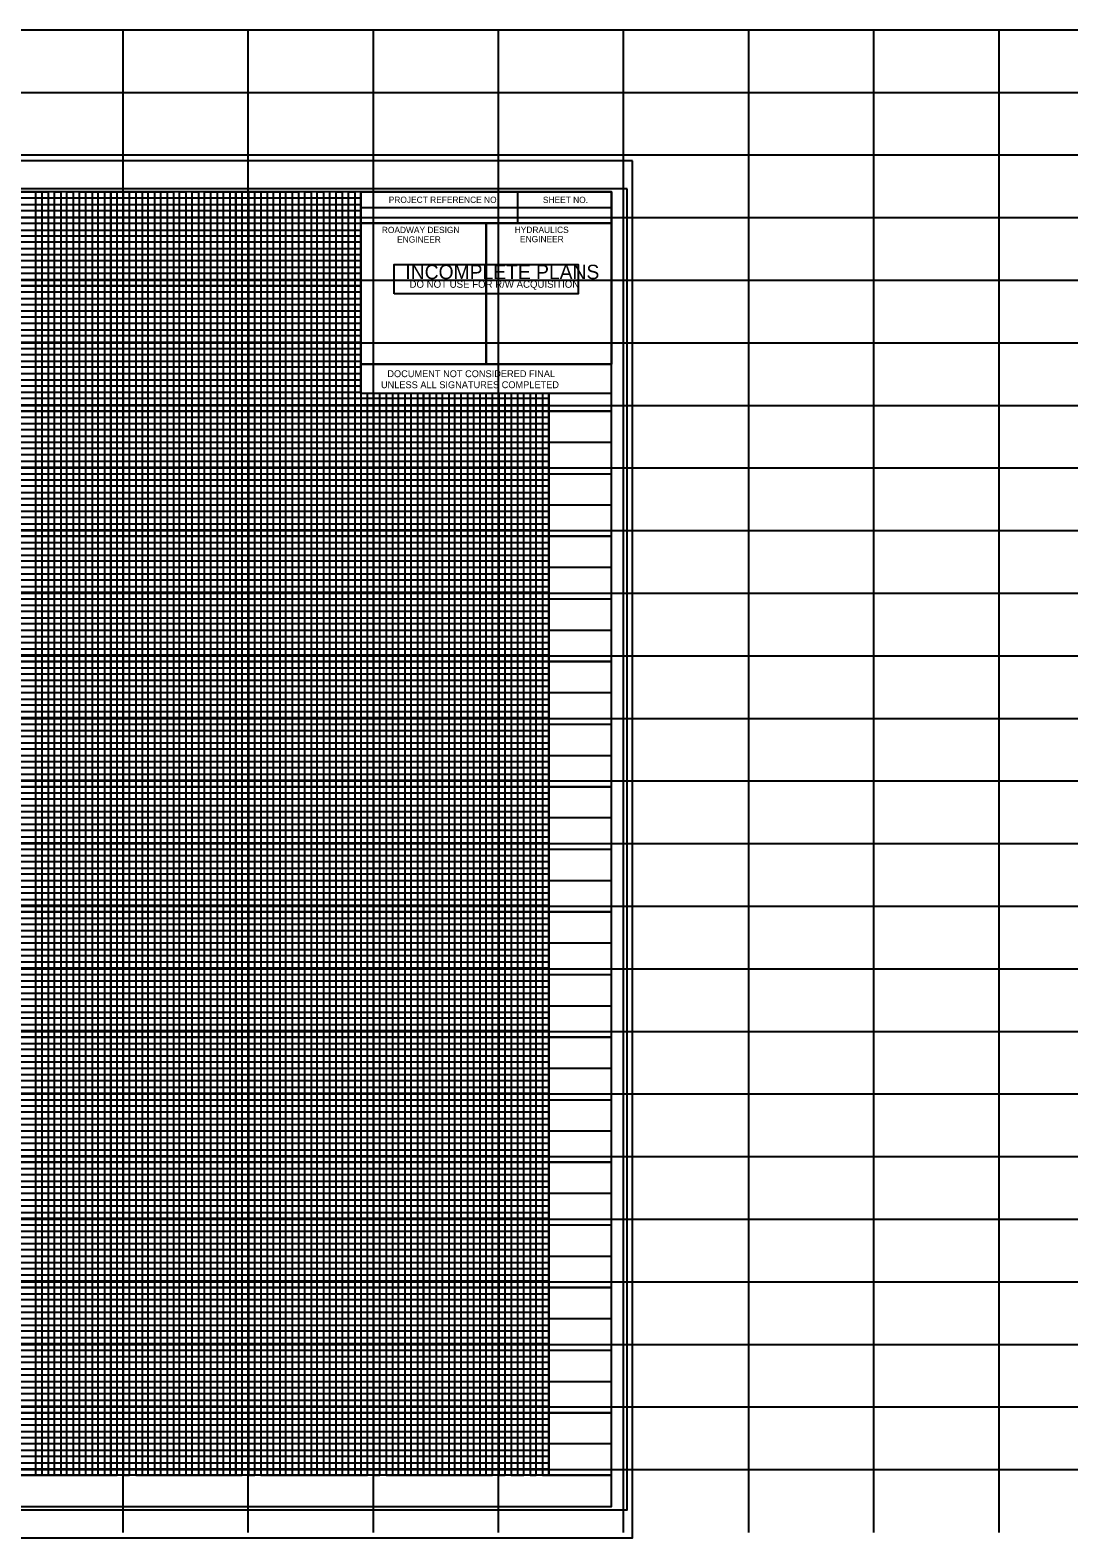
# Model space of a CAD drawing. Extents: x 553912 to 567693, y 512355 to 537539.
# Drawn here: x 560975 to 561805, y 521050 to 522255 of the extents above; entities that cross this region are included whole.
import ezdxf

# ---------------------------------------------------------------- set-up
doc = ezdxf.new("R2010")
doc.units = 0
for name, color, linetype in [('Default', 7, 'Continuous'), ('Old_Level_42', 7, 'Continuous'), ('Old_Level_51', 7, 'Continuous'), ('Old_Level_53', 7, 'Continuous'), ('Old_Level_54', 7, 'Continuous'), ('Prop ROW Permanent Easement CELL', 7, 'Continuous'), ('Sheet Profile Grid Major CELL', 7, 'Continuous'), ('Sheet Row Area Data CELL', 7, 'Continuous'), ('Sheet Sticker Exception Certification CELL', 7, 'Continuous'), ('Sheet Summary Guardrail CELL', 7, 'Continuous')]:
    doc.layers.add(name, color=color, linetype=linetype)

msp = doc.modelspace()

# ---------------------------------------------------------------- linework, layer by layer
at = {"layer": 'Default'}
for points in [[(561456.7, 522150.4), (559772.7, 522150.4), (559772.7, 521050.4), (561456.7, 521050.4)], [(561266.2, 522044.1), (561266.2, 522067.6), (561413.2, 522067.6), (561413.2, 522044.1)]]:
    msp.add_lwpolyline(points, close=True, dxfattribs=at)
at = {"layer": 'Old_Level_42'}
for p, q in [((560989.7, 522125.4), (560989.7, 521100.4)), ((561039.7, 522125.4), (561039.7, 521100.4)), ((561089.7, 522125.4), (561089.7, 521100.4)), ((561139.7, 522125.4), (561139.7, 521100.4)), ((561189.7, 522125.4), (561189.7, 521100.4)), ((559939.7, 522100.4), (561239.6, 522100.4)), ((559939.7, 522050.4), (561239.6, 522050.4)), ((559939.7, 522000.4), (561239.6, 522000.4)), ((561239.7, 521100.4), (561239.7, 521987.9)), ((561289.7, 521100.4), (561289.7, 521964.4)), ((561339.7, 521100.4), (561339.7, 521964.4)), ((561389.7, 521100.4), (561389.7, 521964.4)), ((559939.7, 521950.4), (561439.7, 521950.4)), ((559939.7, 521900.4), (561439.7, 521900.4)), ((559939.7, 521850.4), (561439.7, 521850.4)), ((559939.7, 521800.4), (561439.7, 521800.4)), ((559939.7, 521750.4), (561439.7, 521750.4)), ((559939.7, 521700.4), (561439.7, 521700.4)), ((559939.7, 521650.4), (561439.7, 521650.4)), ((559939.7, 521600.4), (561439.7, 521600.4)), ((559939.7, 521550.4), (561439.7, 521550.4)), ((559939.7, 521500.4), (561439.7, 521500.4)), ((559939.7, 521450.4), (561439.7, 521450.4)), ((559939.7, 521400.4), (561439.7, 521400.4)), ((559939.7, 521350.4), (561439.7, 521350.4)), ((559939.7, 521300.4), (561439.7, 521300.4)), ((559939.7, 521250.4), (561439.7, 521250.4)), ((559939.7, 521200.4), (561439.7, 521200.4)), ((559939.7, 521150.4), (561439.7, 521150.4))]:
    msp.add_line(p, q, dxfattribs=at)
at = {"layer": 'Old_Level_51'}
msp.add_lwpolyline([(561452.2, 522128), (559785.7, 522128), (559785.7, 521072.9), (561452.2, 521072.9)], close=True, dxfattribs=at)
at = {"layer": 'Old_Level_53'}
for p, q in [((561364.7, 522125.4), (561364.7, 522100.4)), ((561239.6, 522112.9), (561439.7, 522112.9)), ((561339.7, 522100.4), (561339.7, 521987.9)), ((561439.7, 521100.4), (559939.7, 521100.4))]:
    msp.add_line(p, q, dxfattribs=at)
for points in [[(561439.7, 522125.4), (559939.7, 522125.4), (559939.7, 521075.4), (561439.7, 521075.4)], [(561239.6, 522125.4), (561439.7, 522125.4), (561439.7, 522100.4), (561239.6, 522100.4)], [(561239.6, 522100.4), (561339.7, 522100.4), (561339.7, 521987.9), (561239.6, 521987.9)], [(561339.7, 522100.4), (561439.7, 522100.4), (561439.7, 521987.9), (561339.7, 521987.9)]]:
    msp.add_lwpolyline(points, close=True, dxfattribs=at)
at = {"layer": 'Old_Level_54'}
for points in [[(560939.7, 522125.4), (560989.7, 522125.4), (560989.7, 521100.4), (561039.7, 521100.4), (561039.7, 522125.4), (561089.7, 522125.4), (561089.7, 521100.4), (561139.7, 521100.4), (561139.7, 522125.4), (561189.7, 522125.4), (561189.7, 521100.4), (561239.7, 521100.4), (561239.7, 522125.4), (561266, 522125.4)], [(561239.6, 522050.4), (559939.8, 522050.4), (559939.8, 522100.4), (561239.6, 522100.4)], [(561439.7, 521950.4), (559939.7, 521950.4), (559939.7, 522000.4), (561239.6, 522000.4)], [(561289.7, 521964.4), (561289.7, 521100.4), (561339.7, 521100.4), (561339.7, 521964.4)], [(561389.7, 521964.4), (561389.7, 521100.4), (561439.7, 521100.4)], [(561439.7, 521850.4), (559939.7, 521850.4), (559939.7, 521900.4), (561439.7, 521900.4)], [(561439.7, 521750.4), (559939.7, 521750.4), (559939.7, 521800.4), (561439.7, 521800.4)], [(561439.7, 521650.4), (559939.7, 521650.4), (559939.7, 521700.4), (561439.7, 521700.4)], [(561439.7, 521550.4), (559939.7, 521550.4), (559939.7, 521600.4), (561439.7, 521600.4)], [(561439.7, 521450.4), (559939.7, 521450.4), (559939.7, 521500.4), (561439.7, 521500.4)], [(561439.7, 521350.4), (559939.7, 521350.4), (559939.7, 521400.4), (561439.7, 521400.4)], [(561439.7, 521250.4), (559939.7, 521250.4), (559939.7, 521300.4), (561439.7, 521300.4)], [(561439.7, 521150.4), (559939.7, 521150.4), (559939.7, 521200.4), (561439.7, 521200.4)]]:
    msp.add_lwpolyline(points, dxfattribs=at)
at = {"layer": 'Prop ROW Permanent Easement CELL'}
for points in [[(560964.7, 521100.4), (561014.7, 521100.4), (561014.7, 522125.4), (561064.7, 522125.4), (561064.7, 521100.4), (561114.7, 521100.4), (561114.7, 522125.4), (561164.7, 522125.4), (561164.7, 521100.4), (561214.7, 521100.4), (561214.7, 522125.4)], [(559939.7, 522075.4), (561239.6, 522075.4)], [(561239.6, 522025.4), (559939.7, 522025.4), (559939.7, 521975.4), (561239.6, 521975.4)], [(561264.7, 521964.4), (561264.7, 521100.4), (561314.7, 521100.4), (561314.7, 521964.4)], [(561364.7, 521964.4), (561364.7, 521100.4)], [(561439.7, 521925.4), (559939.7, 521925.4), (559939.7, 521875.4), (561439.7, 521875.4)], [(561439.7, 521825.4), (559939.7, 521825.4), (559939.7, 521775.4), (561439.7, 521775.4)], [(561439.7, 521725.4), (559939.7, 521725.4), (559939.7, 521675.4), (561439.7, 521675.4)], [(561439.7, 521625.4), (559939.7, 521625.4), (559939.7, 521575.4), (561439.7, 521575.4)], [(561439.7, 521525.4), (559939.7, 521525.4), (559939.7, 521475.4), (561439.7, 521475.4)], [(561439.7, 521425.4), (559939.7, 521425.4), (559939.7, 521375.4), (561439.7, 521375.4)], [(561439.7, 521325.4), (559939.7, 521325.4), (559939.7, 521275.4), (561439.7, 521275.4)], [(561439.7, 521225.4), (559939.7, 521225.4), (559939.7, 521175.4), (561439.7, 521175.4)], [(561439.7, 521125.4), (559939.7, 521125.4)]]:
    msp.add_lwpolyline(points, dxfattribs=at)
at = {"layer": 'Sheet Profile Grid Major CELL'}
for p, q in [((563849.5, 522254.7), (557249.5, 522254.7)), ((561049.5, 521054.7), (561049.5, 522254.7)), ((561149.5, 521054.7), (561149.5, 522254.7)), ((561249.5, 521054.7), (561249.5, 522254.7)), ((561349.5, 521054.7), (561349.5, 522254.7)), ((561449.5, 521054.7), (561449.5, 522254.7)), ((561549.5, 521054.7), (561549.5, 522254.7)), ((561649.5, 521054.7), (561649.5, 522254.7)), ((561749.5, 521054.7), (561749.5, 522254.7)), ((563849.5, 522204.7), (557249.5, 522204.7)), ((563849.5, 522154.7), (557249.5, 522154.7)), ((563849.5, 522104.7), (557249.5, 522104.7)), ((563849.5, 522054.7), (557249.5, 522054.7)), ((563849.5, 522004.7), (557249.5, 522004.7)), ((563849.5, 521954.7), (557249.5, 521954.7)), ((563849.5, 521904.7), (557249.5, 521904.7)), ((563849.5, 521854.7), (557249.5, 521854.7)), ((563849.5, 521804.7), (557249.5, 521804.7)), ((563849.5, 521754.7), (557249.5, 521754.7)), ((563849.5, 521704.7), (557249.5, 521704.7)), ((563849.5, 521654.7), (557249.5, 521654.7)), ((563849.5, 521604.7), (557249.5, 521604.7)), ((563849.5, 521554.7), (557249.5, 521554.7)), ((563849.5, 521504.7), (557249.5, 521504.7)), ((563849.5, 521454.7), (557249.5, 521454.7)), ((563849.5, 521404.7), (557249.5, 521404.7)), ((563849.5, 521354.7), (557249.5, 521354.7)), ((563849.5, 521304.7), (557249.5, 521304.7)), ((563849.5, 521254.7), (557249.5, 521254.7)), ((563849.5, 521204.7), (557249.5, 521204.7)), ((563849.5, 521154.7), (557249.5, 521154.7)), ((563849.5, 521104.7), (557249.5, 521104.7))]:
    msp.add_line(p, q, dxfattribs=at)
at = {"layer": 'Sheet Row Area Data CELL'}
for p, q in [((561456.7, 522150.4), (559772.7, 522150.4)), ((559772.7, 521050.4), (561456.7, 521050.4))]:
    msp.add_line(p, q, dxfattribs=at)
at = {"layer": 'Sheet Sticker Exception Certification CELL'}
for p, q in [((561239.6, 521964.4), (561239.6, 521987.9)), ((561239.6, 521987.9), (561439.6, 521987.9)), ((561439.6, 521987.9), (561439.6, 521964.4)), ((561439.6, 521964.4), (561239.6, 521964.4))]:
    msp.add_line(p, q, dxfattribs=at)
at = {"layer": 'Sheet Summary Guardrail CELL'}
for p, q in [((561389.7, 521945.4), (559989.7, 521945.4)), ((559989.7, 521940.4), (561389.7, 521940.4)), ((561389.7, 521920.4), (559989.7, 521920.4))]:
    msp.add_line(p, q, dxfattribs=at)
for points in [[(560974.7, 521100.4), (560979.7, 521100.4), (560979.7, 522125.4), (560984.7, 522125.4), (560984.7, 521100.4), (560994.7, 521100.4), (560994.7, 522125.4), (560999.7, 522125.4), (560999.7, 521100.4), (561004.7, 521100.4), (561004.7, 522125.4), (561009.7, 522125.4), (561009.7, 521100.4)], [(561009.7, 521100.4), (561019.7, 521100.4), (561019.7, 522125.4), (561024.7, 522125.4), (561024.7, 521100.4), (561029.7, 521100.4), (561029.7, 522125.4), (561034.7, 522125.4), (561034.7, 521100.4), (561044.7, 521100.4), (561044.7, 522125.4), (561049.7, 522125.4), (561049.7, 521100.4), (561054.7, 521100.4), (561054.7, 522125.4), (561059.7, 522125.4), (561059.7, 521100.4), (561069.7, 521100.4), (561069.7, 522125.4), (561074.7, 522125.4), (561074.7, 521100.4), (561079.7, 521100.4), (561079.7, 522125.4), (561084.7, 522125.4), (561084.7, 521100.4), (561094.7, 521100.4), (561094.7, 522125.4), (561099.7, 522125.4), (561099.7, 521100.4), (561104.7, 521100.4), (561104.7, 522125.4), (561109.7, 522125.4), (561109.7, 521100.4), (561119.7, 521100.4), (561119.7, 522125.4), (561124.7, 522125.4), (561124.7, 521100.4), (561129.7, 521100.4), (561129.7, 522125.4), (561134.7, 522125.4), (561134.7, 521100.4), (561144.7, 521100.4), (561144.7, 522125.4), (561149.7, 522125.4), (561149.7, 521100.4), (561154.7, 521100.4), (561154.7, 522125.4), (561159.7, 522125.4), (561159.7, 521100.4), (561169.7, 521100.4), (561169.7, 522125.4), (561174.7, 522125.4), (561174.7, 521100.4), (561179.7, 521100.4), (561179.7, 522125.4), (561184.7, 522125.4), (561184.7, 521100.4), (561194.7, 521100.4), (561194.7, 522125.4), (561199.7, 522125.4), (561199.7, 521100.4), (561204.7, 521100.4), (561204.7, 522125.4), (561209.7, 522125.4), (561209.7, 521100.4), (561219.7, 521100.4), (561219.7, 522125.4), (561224.7, 522125.4), (561224.7, 521100.4), (561229.7, 521100.4), (561229.7, 522125.4), (561234.7, 522125.4), (561234.7, 521100.4), (561244.7, 521100.4), (561244.7, 521964.4)], [(561239.6, 522120.4), (559989.7, 522120.4), (559989.7, 522115.4), (561239.6, 522115.4)], [(561239.6, 522110.4), (559989.7, 522110.4), (559989.7, 522105.4), (561239.6, 522105.4)], [(561239.6, 522094.7), (559990.7, 522094.7), (559990.7, 522090.4), (561239.6, 522090.4)], [(561239.6, 522085.4), (559989.7, 522085.4), (559989.7, 522080.4), (561239.6, 522080.4)], [(561239.6, 522070.4), (559989.7, 522070.4), (559989.7, 522065.4), (561239.6, 522065.4)], [(561239.6, 522060.4), (559989.7, 522060.4), (559989.7, 522055.4), (561239.6, 522055.4)], [(561239.6, 522045.4), (559989.7, 522045.4), (559989.7, 522040.4), (561239.6, 522040.4)], [(561239.6, 522035.4), (559989.7, 522035.4), (559989.7, 522030.4), (561239.6, 522030.4)], [(561239.6, 522020.4), (559989.7, 522020.4), (559989.7, 522015.4), (561239.6, 522015.4)], [(561239.6, 522010.4), (559989.7, 522010.4), (559989.7, 522005.4), (561239.6, 522005.4)], [(561239.6, 521995.4), (559989.7, 521995.4), (559989.7, 521990.4), (561239.6, 521990.4)], [(561239.6, 521985.4), (559989.7, 521985.4), (559989.7, 521985.4), (559989.7, 521965.4), (561239.6, 521965.4)], [(559989.7, 521980.4), (561239.6, 521980.4)], [(561239.6, 521970.4), (559989.7, 521970.4)], [(561389.7, 521960.4), (559989.7, 521960.4), (559989.7, 521955.4), (561389.7, 521955.4)], [(561249.7, 521964.4), (561249.7, 521100.4), (561254.7, 521100.4), (561254.7, 521964.4)], [(561259.7, 521964.4), (561259.7, 521100.4), (561269.7, 521100.4), (561269.7, 521964.4)], [(561274.7, 521964.4), (561274.7, 521100.4), (561279.7, 521100.4), (561279.7, 521964.4)], [(561284.7, 521964.4), (561284.7, 521100.4), (561294.7, 521100.4), (561294.7, 521964.4)], [(561299.7, 521964.4), (561299.7, 521100.4), (561304.7, 521100.4), (561304.7, 521964.4)], [(561309.7, 521964.4), (561309.7, 521100.4), (561319.7, 521100.4), (561319.7, 521964.4)], [(561324.7, 521964.4), (561324.7, 521100.4)], [(561324.7, 521100.4), (561329.7, 521100.4), (561329.7, 521964.4)], [(561334.7, 521964.4), (561334.7, 521100.4), (561344.7, 521100.4), (561344.7, 521964.4)], [(561349.7, 521964.4), (561349.7, 521100.4), (561354.7, 521100.4), (561354.7, 521964.4)], [(561359.7, 521964.4), (561359.7, 521100.4), (561369.7, 521100.4), (561369.7, 521964.4)], [(561374.7, 521964.4), (561374.7, 521100.4), (561379.7, 521100.4), (561379.7, 521964.4)], [(561384.7, 521964.4), (561384.7, 521100.4), (561394.7, 521100.4)], [(561389.7, 521935.4), (559989.7, 521935.4), (559989.7, 521930.4), (561389.7, 521930.4)], [(561389.7, 521915.4), (559989.7, 521915.4), (559989.7, 521910.4), (561389.7, 521910.4)], [(561389.7, 521905.4), (559989.7, 521905.4)], [(559989.7, 521895.4), (561389.7, 521895.4)], [(561389.7, 521890.4), (559989.7, 521890.4), (559989.7, 521885.4), (561389.7, 521885.4)], [(561389.7, 521880.4), (559989.7, 521880.4), (559989.7, 521870.4), (561389.7, 521870.4)], [(561389.7, 521865.4), (559989.7, 521865.4), (559989.7, 521860.4), (561389.7, 521860.4)], [(561389.7, 521855.4), (559989.7, 521855.4), (559989.7, 521845.4), (561389.7, 521845.4)], [(561389.7, 521840.4), (559989.7, 521840.4), (559989.7, 521835.4), (561389.7, 521835.4)], [(561389.7, 521830.4), (559989.7, 521830.4), (559989.7, 521820.4), (561389.7, 521820.4)], [(561389.7, 521815.4), (559989.7, 521815.4), (559989.7, 521810.4), (561389.7, 521810.4)], [(561389.7, 521805.4), (559989.7, 521805.4), (559989.7, 521795.4), (561389.7, 521795.4)], [(561389.7, 521790.4), (559989.7, 521790.4), (559989.7, 521785.4), (561389.7, 521785.4)], [(561389.7, 521780.4), (559989.7, 521780.4), (559989.7, 521770.4), (561389.7, 521770.4)], [(561389.7, 521765.4), (559989.7, 521765.4), (559989.7, 521760.4), (561389.7, 521760.4)], [(561389.7, 521755.4), (559989.7, 521755.4), (559989.7, 521745.4), (561389.7, 521745.4)], [(561389.7, 521740.4), (559989.7, 521740.4), (559989.7, 521735.4), (561389.7, 521735.4)], [(561389.7, 521730.4), (559989.7, 521730.4), (559989.7, 521720.4), (561389.7, 521720.4)], [(561389.7, 521715.4), (559989.7, 521715.4), (559989.7, 521710.4), (561389.7, 521710.4)], [(561389.7, 521705.4), (559989.7, 521705.4), (559989.7, 521695.4), (561389.7, 521695.4)], [(561389.7, 521690.4), (559989.7, 521690.4), (559989.7, 521685.4), (561389.7, 521685.4)], [(561389.7, 521680.4), (559989.7, 521680.4), (559989.7, 521670.4), (561389.7, 521670.4)], [(561389.7, 521665.4), (559989.7, 521665.4), (559989.7, 521660.4), (561389.7, 521660.4)], [(561389.7, 521655.4), (559989.7, 521655.4), (559989.7, 521645.4), (561389.7, 521645.4)], [(561389.7, 521640.4), (559989.7, 521640.4), (559989.7, 521635.4), (561389.7, 521635.4)], [(561389.7, 521630.4), (559989.7, 521630.4), (559989.7, 521620.4), (561389.7, 521620.4)], [(561389.7, 521615.4), (559989.7, 521615.4), (559989.7, 521610.4), (561389.7, 521610.4)], [(561389.7, 521605.4), (559989.7, 521605.4)], [(559989.7, 521595.4), (561389.7, 521595.4)], [(561389.7, 521590.4), (559989.7, 521590.4), (559989.7, 521585.4), (561389.7, 521585.4)], [(561389.7, 521580.4), (559989.7, 521580.4), (559989.7, 521570.4), (561389.7, 521570.4)], [(561389.7, 521565.4), (559989.7, 521565.4), (559989.7, 521560.4), (561389.7, 521560.4)], [(561389.7, 521555.4), (559989.7, 521555.4), (559989.7, 521545.4), (561389.7, 521545.4)], [(561389.7, 521540.4), (559989.7, 521540.4), (559989.7, 521535.4), (561389.7, 521535.4)], [(561389.7, 521530.4), (559989.7, 521530.4), (559989.7, 521520.4), (561389.7, 521520.4)], [(561389.7, 521515.4), (559989.7, 521515.4), (559989.7, 521510.4), (561389.7, 521510.4)], [(561389.7, 521505.4), (559989.7, 521505.4), (559989.7, 521495.4), (561389.7, 521495.4)], [(561389.7, 521490.4), (559989.7, 521490.4), (559989.7, 521485.4), (561389.7, 521485.4)], [(561389.7, 521480.4), (559989.7, 521480.4), (559989.7, 521470.4), (561389.7, 521470.4)], [(561389.7, 521465.4), (559989.7, 521465.4), (559989.7, 521460.4), (561389.7, 521460.4)], [(561389.7, 521455.4), (559989.7, 521455.4), (559989.7, 521445.4), (561389.7, 521445.4)], [(561389.7, 521440.4), (559989.7, 521440.4), (559989.7, 521435.4), (561389.7, 521435.4)], [(561389.7, 521430.4), (559989.7, 521430.4), (559989.7, 521420.4), (561389.7, 521420.4)], [(561389.7, 521415.4), (559989.7, 521415.4), (559989.7, 521410.4), (561389.7, 521410.4)], [(561389.7, 521405.4), (559989.7, 521405.4), (559989.7, 521395.4), (561389.7, 521395.4)], [(561389.7, 521390.4), (559989.7, 521390.4), (559989.7, 521385.4), (561389.7, 521385.4)], [(561389.7, 521380.4), (559989.7, 521380.4), (559989.7, 521370.4), (561389.7, 521370.4)], [(561389.7, 521365.4), (559989.7, 521365.4), (559989.7, 521360.4), (561389.7, 521360.4)], [(561389.7, 521355.4), (559989.7, 521355.4), (559989.7, 521345.4), (561389.7, 521345.4)], [(561389.7, 521340.4), (559989.7, 521340.4), (559989.7, 521335.4), (561389.7, 521335.4)], [(561389.7, 521330.4), (559989.7, 521330.4), (559989.7, 521320.4), (561389.7, 521320.4)], [(561389.7, 521315.4), (559989.7, 521315.4), (559989.7, 521310.4), (561389.7, 521310.4)], [(561389.7, 521305.4), (559989.7, 521305.4)], [(559989.7, 521295.4), (561389.7, 521295.4)], [(561389.7, 521290.4), (559989.7, 521290.4), (559989.7, 521285.4), (561389.7, 521285.4)], [(561389.7, 521280.4), (559989.7, 521280.4)], [(559989.7, 521270.4), (561389.7, 521270.4)], [(561389.7, 521265.4), (559989.7, 521265.4), (559989.7, 521260.4), (561389.7, 521260.4)], [(561389.7, 521255.4), (559989.7, 521255.4), (559989.7, 521245.4), (561389.7, 521245.4)], [(561389.7, 521240.4), (559989.7, 521240.4), (559989.7, 521235.4), (561389.7, 521235.4)], [(561389.7, 521230.4), (559989.7, 521230.4), (559989.7, 521220.4), (561389.7, 521220.4)], [(561389.7, 521215.4), (559989.7, 521215.4), (559989.7, 521210.4), (561389.7, 521210.4)], [(561389.7, 521205.4), (559989.7, 521205.4), (559989.7, 521195.4), (561389.7, 521195.4)], [(561389.7, 521190.4), (559989.7, 521190.4), (559989.7, 521185.4), (561389.7, 521185.4)], [(561389.7, 521180.4), (559989.7, 521180.4), (559989.7, 521170.4), (561389.7, 521170.4)], [(561389.7, 521165.4), (559989.7, 521165.4), (559989.7, 521160.4), (561389.7, 521160.4)], [(561389.7, 521155.4), (559989.7, 521155.4), (559989.7, 521145.4), (561389.7, 521145.4)], [(561389.7, 521140.4), (559989.7, 521140.4), (559989.7, 521135.4), (561389.7, 521135.4)], [(561389.7, 521130.4), (559989.7, 521130.4), (559989.7, 521120.4), (561389.7, 521120.4)], [(561389.7, 521115.4), (559989.7, 521115.4), (559989.7, 521110.4), (561389.7, 521110.4)], [(561389.7, 521105.4), (559989.7, 521105.4)]]:
    msp.add_lwpolyline(points, dxfattribs=at)

# ---------------------------------------------------------------- texts
at = {"layer": 'Default'}
for s, height, p in [('INCOMPLETE PLANS', 11.52, (561275.1, 522055.8)), ('DO NOT USE FOR R/W ACQUISITION', 5.76, (561278.4, 522048.9))]:
    msp.add_text(s, height=height, dxfattribs=at).set_placement(p)
at = {"layer": 'Old_Level_53'}
for s, p in [('PROJECT REFERENCE NO.', (561261.8, 522116.7)), ('SHEET NO.', (561385, 522116.6)), ('ROADWAY DESIGN', (561256.3, 522092.6)), ('ENGINEER', (561268.5, 522085)), ('HYDRAULICS', (561362.5, 522092.7)), ('ENGINEER', (561366.7, 522085.3))]:
    msp.add_text(s, height=5, dxfattribs=at).set_placement(p)
at = {"layer": 'Sheet Sticker Exception Certification CELL'}
for s, p in [('DOCUMENT NOT CONSIDERED FINAL', (561260.7, 521977.5)), ('UNLESS ALL SIGNATURES COMPLETED', (561255.6, 521968.7))]:
    msp.add_text(s, height=5.5, dxfattribs=at).set_placement(p)

doc.saveas('drawing.dxf')
